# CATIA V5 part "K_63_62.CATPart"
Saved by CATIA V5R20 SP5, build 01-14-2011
Part number: 63
Bounding box of the stored display mesh (mm): x 0 to 50, y -88 to 212, z -27 to 87
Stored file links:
  G:\Khaled_CFAO_2011\ST2M\ST2M_GR1\lpierredon\Khaled\CAD_thinkMOTION\K_63_62.CATPart
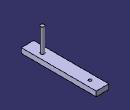
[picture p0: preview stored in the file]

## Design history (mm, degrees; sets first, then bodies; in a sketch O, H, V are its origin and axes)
Body1 (main body)
  Sketch1 on yz-plane, origin (0, 0, 0), H (0, 1, 0), V (0, 0, 1)
    line L1 (-88, -7) -> (212, -7)
    line L2 (212, -7) -> (212, -27)
    line L3 (212, -27) -> (-88, -27)
    line L4 (-88, -27) -> (-88, -7)
    distance L1 L3 = 20
    distance L2 L4 = 300
    horizontal: L1 H, L3 H
    vertical: L2 V, L4 V
  Pad1: profile Sketch1, direction (1, 0, 0), length 50
  Sketch2 on face of Pad1 from Sketch1.L1, origin (0, 0, -7), H (1, 0, 0), V (0, 1, 0)
    circle A1 centre (25, -28) radius 7.5
    point P1 (25, -28)
    reference projected line E1 (50, 212) -> (50, -88) from edge [face of Pad1 from Sketch1.L1 | end face of Pad1]
    reference projected line E2 (0, 212) -> (0, -88) from edge [start face of Pad1 | face of Pad1 from Sketch1.L1]
    reference projected line E3 (0, 212) -> (50, 212) from edge [face of Pad1 from Sketch1.L1 | face of Pad1 from Sketch1.L2]
    distance P1 E3 = 240
    radius A1 = 7.5
    equidistance: E1 E2 P1
  Pad2: profile Sketch2, direction (0, 0, 1), length 94
  Sketch3 on face of Pad1 from Sketch1.L1, origin (22.0577, 157.0111, -7), H (1, 0, 0), V (0, 1, 0)
    point P1 (2.9423, 4.9889)
    reference projected line E1 (27.9423, 54.9889) -> (27.9423, -245.0111) from edge [face of Pad1 from Sketch1.L1 | end face of Pad1]
    reference projected line E2 (-22.0577, 54.9889) -> (-22.0577, -245.0111) from edge [start face of Pad1 | face of Pad1 from Sketch1.L1]
    reference projected line E3 (-22.0577, 54.9889) -> (27.9423, 54.9889) from edge [face of Pad1 from Sketch1.L1 | face of Pad1 from Sketch1.L2]
    distance P1 E3 = 50
    equidistance: E1 E2 P1
  Hole1: placed by Sketch3, at (25, 162, -7) direction (0, 0, -1), diameter 11, through (limit type 6)
  Chamfer1: length 5, angle 45, on edge [face of Pad1 from Sketch1.L3 | face of Pad1 from Sketch1.L4]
